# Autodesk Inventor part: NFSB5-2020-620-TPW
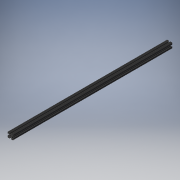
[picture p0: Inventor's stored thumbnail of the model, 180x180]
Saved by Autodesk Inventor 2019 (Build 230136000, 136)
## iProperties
Created: 2022-11
Part Number: NFSB5-2020-620-TPW
Material: Generic
Catalog Web Link: www.cadenas.de
Description: NFS5-2020, NFSB5-2020, HFS5-2020, HFSB5-2020, CAF5-2020, HFSY5-2020, NFSF5-2020, HFSF5-2020, HFSFB5-2020, NFST5-2020, HFST5-2020, HFSTB5-2020, HFSH5-2020, HFSC5
Vendor: MISUMI
Document SubType Name: Modeling
Designer: psAdmin
Manufacturer: MISUMI
Mass: 112.393 g
Surface Area: 1082.73 cm^2
Volume: 112.393 cm^3
Density: 1 g/cm^3
Appearance: PSOLRGB-175-175-175
Category: PARTsolutions
Company: MISUMI
Title: NFSB5-2020-620-TPW
Author: Cadenas PARTsolutions
Comments: HFS5 Series Aluminum Extrusions 20 Square -1 Slot-
PSOL_IDENT_0: {$CADENAS_DATA/23d-libs/misumi/metric/38_al_extrusions_blackets/5/hfs5_2020.prj},686 {VTYP=3D},{NB=N
PSOL_IDENT_1: FSB5-2020-620-TPW},{LINA=NFSB5-2020-620-TPW},{NN=NFS5-2020, NFSB5-2020, HFS5-2020, HFSB5-2020, CAF5-
PSOL_IDENT_2: 2020, HFSY5-2020, NFSF5-2020, HFSF5-2020, HFSFB5-2020, NFST5-2020, HFST5-2020, HFSTB5-2020, HFSH5-20
PSOL_IDENT_3: 20, HFSC5-2020},{DATE=08.06.2021 08:25:16},{GEOMDATE=18.06.2019 07:59:14},{VERSION=},{LINEID=20},{WB
PSOL_IDENT_4: VAR=L,ALT1,ALT2,ALT4,ALT5,CP5,DL5,DR5,ALT6,ALT9,ALT10,ALT11,HP6,NHL6,DL6,NHR6,DR6,ALT7,ALT8,NH9,AH,B
PSOL_IDENT_5: H,CH,DH,EH,NH10,AV,BV,CV,DV,EV,NH11,AP,BP,CP,DP,EP,ALT12,ALT13,Z,NH12,XA,XB,XC,XD,XE,NH13,YA,YB,YC,Y
PSOL_IDENT_6: D,YE,ALT16,HP16,DL16,DR16,ALT17,HQ17,JLP,ALT20},{WBNUMERIC=L,NH9,AH,BH,CH,DH,EH,NH10,AV,BV,CV,DV,EV,
PSOL_IDENT_7: NH11,AP,BP,CP,DP,EP,NH12,XA,XB,XC,XD,XE,NH13,YA,YB,YC,YD,YE,HQ17,JLP}  {NB=NFSB5-2020-620-TPW},{LINA=
PSOL_IDENT_8: NFSB5-2020-620-TPW},{KT=DUMMY},{PN=NFSB5-2020-620-TPW},{TPS=NFSB5-2020},{MAT=6063-T5 Aluminum Alloy}
PSOL_IDENT_9: ,{ST=Black Anodize},{FRMW=20},{FRMH=20},{FRD=4.2},{L=620},{MASS=0.5},{SA=183},{LX=0.742x10^4},{LY=0.
PSOL_IDENT_10: 742x10^4},{ALT1=TPW},{M1=5},{DPL1=15},{DPR1=15},{ALT1PN=-TPW},{ALT2=},{ALT2ALG= '','Not applicable'
PSOL_IDENT_11: },{M2=0},{DP2=0},{ALT2PN=},{ALT4=},{ALT4ALG= '', 'w/o SC (High Precision Cut)', 'SC', 'with SC (High
PSOL_IDENT_12: Precision Cut)' },{ALT4PN=},{ALT5=},{ALT5ALG= '','w/o 45 Degree Cut','1','with 45 Degree Cut' },{CP
PSOL_IDENT_13: 5=},{CP5ALG= '','N/A' },{DL5=},{DL5ALG= '','N/A' },{DR5=},{DR5ALG= '','N/A' },{FRMLALT5=0},{FRMRALT5=
PSOL_IDENT_14: 0},{ALT5PN=},{ALT6=},{ALT6ALG= '','w/o Fastening Location Wrench Access Hole Alterations','1','with
PSOL_IDENT_15: Fastening Location Wrench Access Hole Alterations' },{ALT9=},{ALT9ALG= '','w/o Location Specified Wr
PSOL_IDENT_16: ench Access Hole Alteratons (Horizontal)','1','with Location Specified Wrench Access Hole Alteratons
PSOL_IDENT_17: (Horizontal)' },{ALT10=},{ALT10ALG= '','w/o Location Specified Wrench Access Hole Alteratons (Verti
PSOL_IDENT_18: cal)','1','with Location Specified Wrench Access Hole Alteratons (Vertical)' },{ALT11=},{ALT11ALG= ''
PSOL_IDENT_19: ,'w/o Location Specified Wrench Access Hole Alteratons (Crisscross)','1','with Location Specified Wr
PSOL_IDENT_20: ench Access Hole Alteratons (Crisscross)' },{HP6=},{HP6ALG= '','N/A' },{NHL6=},{NHL6ALG= '','N/A' },
PSOL_IDENT_21: {DL6=},{DL6ALG= '','N/A' },{NHR6=},{NHR6ALG= '','N/A' },{DR6=},{DR6ALG= '','N/A' },{HL6=0.000},{HL6D=
PSOL_IDENT_22: 0},{HR6=0.000},{HR6D=0},{J6=0},{J6D=0},{K6=0},{K6D=0},{DD6=0.00},{DD6ALG=0},{ALT7=},{ALT7ALG= '','N/
PSOL_IDENT_23: A' },{ALT8=},{ALT8ALG= '','N/A' },{ALT678PN=},{NH9=0},{NH9MAX=5},{NH9ALG=[0]},{AH=0.0},{AHMIN=7},{AH
PSOL_IDENT_24: MAX=615},{AHALG=[0]},{BH=0.0},{BHMIN=2},{BHMAX=617},{BHALG=[0]},{CH=0.0},{CHMIN=2},{CHMAX=619},{CHAL
PSOL_IDENT_25: G=[0]},{DH=0.0},{DHMIN=2},{DHMAX=621},{DHALG=[0]},{EH=0.0},{EHMIN=2},{EHMAX=613},{EHALG=[0]},{NH10=0
PSOL_IDENT_26: },{NH10MAX=5},{NH10ALG=[0]},{AV=0.0},{AVMIN=7},{AVMAX=615},{AVALG=[0]},{BV=0.0},{BVMIN=2},{BVMAX=617
PSOL_IDENT_27: },{BVALG=[0]},{CV=0.0},{CVMIN=2},{CVMAX=619},{CVALG=[0]},{DV=0.0},{DVMIN=2},{DVMAX=621},{DVALG=[0]},
PSOL_IDENT_28: {EV=0.0},{EVMIN=2},{EVMAX=613},{EVALG=[0]},{NH11=0},{NH11MAX=5},{NH11ALG=[0]},{AP=0.0},{APMIN=7},{AP
PSOL_IDENT_29: MAX=615},{APALG=[0]},{BP=0.0},{BPMIN=2},{BPMAX=617},{BPALG=[0]},{CP=0.0},{CPMIN=2},{CPMAX=619},{CPAL
PSOL_IDENT_30: G=[0]},{DP=0.0},{DPMIN=2},{DPMAX=621},{DPALG=[0]},{EP=0.0},{EPMIN=2},{EPMAX=613},{EPALG=[0]},{ALT9PN=
PSOL_IDENT_31: },{ALT10PN=},{ALT11PN=},{ALT91011PN=},{ALT12=},{ALT12ALG= '','w/o Counterbore Hole in Specified Posi
PSOL_IDENT_32: tion (Vertical)','1','with Counterbore Hole in Specified Position (Vertical)' },{ALT13=},{ALT13ALG= ''
PSOL_IDENT_33: ,'w/o Counterbore Hole in Specified Position (Horizontal)','1','with Counterbore Hole in Specified P
PSOL_IDENT_34: osition (Horizontal)' },{Z=},{ZALG= '','N/A' },{DD12=0.0},{DD112=0.0},{NH12=0},{NH12MAX=5},{NH12ALG=
PSOL_IDENT_35: [0]},{XA=0.0},{XAMIN=7},{XAMAX=615},{XAALG=[0]},{XB=0.0},{XBMIN=2},{XBMAX=617},{XBALG=[0]},{XC=0.0},
PSOL_IDENT_36: {XCMIN=2},{XCMAX=619},{XCALG=[0]},{XD=0.0},{XDMIN=2},{XDMAX=621},{XDALG=[0]},{XE=0.0},{XEMIN=2},{XEM
PSOL_IDENT_37: AX=613},{XEALG=[0]},{NH13=0},{NH13MAX=5},{NH13ALG=[0]},{YA=0.0},{YAMIN=7},{YAMAX=615},{YAALG=[0]},{Y
PSOL_IDENT_38: B=0.0},{YBMIN=2},{YBMAX=617},{YBALG=[0]},{YC=0.0},{YCMIN=2},{YCMAX=619},{YCALG=[0]},{YD=0.0},{YDMIN=
PSOL_IDENT_39: 2},{YDMAX=621},{YDALG=[0]},{YE=0.0},{YEMIN=2},{YEMAX=613},{YEALG=[0]},{ALT12PN=},{ALT13PN=},{ALT1213
PSOL_IDENT_40: PN=},{ALT16=},{ALT16ALG= '','w/o M Type Hole Alteration','1','with M Type Hole Alteration' },{HP16=}
PSOL_IDENT_41: ,{HP16ALG= '','N/A' },{DL16=},{DL16ALG= '','N/A' },{DR16=},{DR16ALG= '','N/A' },{H116=0},{D16=0.0},{
PSOL_IDENT_42: ALT16PN=},{ALT17=},{ALT17ALG= '','w/o L Type Hole Alteration (Top)','1','with L Type Hole Alteration
PSOL_IDENT_43: (Top)' },{HQ17=0},{HQ17ALG=0},{JLP=0},{JLPMIN=4.9},{JLPMAX=0},{JLPALG=[0]},{L17=0},{D17=0.0},{ALT17
PSOL_IDENT_44: PN=},{ALT20=},{ALT20PN=},{ERRORALT01=OK},{ERRORALT02=OK},{ERRORALT05=OK},{ERRORALT06091=OK},{ERRORAL
PSOL_IDENT_45: T06092=OK},{ERRORALT06093=OK},{ERRORALT06094=OK},{ERRORALT06101=OK},{ERRORALT06102=OK},{ERRORALT0610
PSOL_IDENT_46: 3=OK},{ERRORALT06104=OK},{ERRORALT06111=OK},{ERRORALT06112=OK},{ERRORALT06113=OK},{ERRORALT06114=OK}
PSOL_IDENT_47: ,{ERRORALT06121=OK},{ERRORALT06122=OK},{ERRORALT06123=OK},{ERRORALT06124=OK},{ERRORALT06131=OK},{ERR
PSOL_IDENT_48: ORALT06132=OK},{ERRORALT06133=OK},{ERRORALT06134=OK},{ERRORALT0616=OK},{ERRORALT06171=OK},{ERRORALT0
PSOL_IDENT_49: 6172=OK},{ERRORALT06173=OK},{ERRORALT0911=OK},{ERRORALT0913=OK},{ERRORALT0916=OK},{ERRORALT0917=OK},
PSOL_IDENT_50: {ERRORALT1011=OK},{ERRORALT1012=OK},{ERRORALT1016=OK},{ERRORALT1017=OK},{ERRORALT1112=OK},{ERRORALT1
PSOL_IDENT_51: 113=OK},{ERRORALT1116=OK},{ERRORALT1117=OK},{ERRORALT1216=OK},{ERRORALT1217=OK},{ERRORALT1316=OK},{E
PSOL_IDENT_52: RRORALT1317=OK},{ERRORALT1617=OK},{ERRORPN=},{TFW=0}
NB: NFSB5-2020-620-TPW
NN: NFS5-2020, NFSB5-2020, HFS5-2020, HFSB5-2020, CAF5-2020, HFSY5-2020, NFSF5-2020, HFSF5-2020, HFSFB5-2020, NFST5-2020, HFST5-2020, HFSTB5-2020, HFSH5-2020, HFSC5
NT: HFS5 Series Aluminum Extrusions 20 Square -1 Slot-
NBSYN: $PN.
LINA: NFSB5-2020-620-TPW
CATALOG: Misumi
PN: NFSB5-2020-620-TPW
TPS: NFSB5-2020
MAT: 6063-T5 Aluminum Alloy
ST: Black Anodize
L: 620
MASS: 0.5
SA: 183
LX: 0.742x10^4
LY: 0.742x10^4
ALT1: with TPW (Tapping on Both Ends)
M1: 5
DPL1: 15
DPR1: 15
ALT2: Not applicable
M2: 0
DP2: 0
ALT4: w/o SC (High Precision Cut)
ALT5: w/o 45 Degree Cut
CP5: N/A
DL5: N/A
DR5: N/A
ALT6: w/o Fastening Location Wrench Access Hole Alterations
ALT9: w/o Location Specified Wrench Access Hole Alteratons (Horizontal)
ALT10: w/o Location Specified Wrench Access Hole Alteratons (Vertical)
ALT11: w/o Location Specified Wrench Access Hole Alteratons (Crisscross)
HP6: N/A
NHL6: N/A
DL6: N/A
NHR6: N/A
DR6: N/A
HL6D: 0
HR6D: 0
J6D: 0
K6D: 0
DD6: 0
ALT7: N/A
ALT8: N/A
NH9: 0
AH: 0
BH: 0
CH: 0
DH: 0
EH: 0
NH10: 0
AV: 0
BV: 0
CV: 0
DV: 0
EV: 0
NH11: 0
AP: 0
BP: 0
CP: 0
DP: 0
EP: 0
ALT12: w/o Counterbore Hole in Specified Position (Vertical)
ALT13: w/o Counterbore Hole in Specified Position (Horizontal)
Z: N/A
DD12: 0
DD112: 0
NH12: 0
XA: 0
XB: 0
XC: 0
XD: 0
XE: 0
NH13: 0
YA: 0
YB: 0
YC: 0
YD: 0
YE: 0
ALT16: w/o M Type Hole Alteration
HP16: N/A
DL16: N/A
DR16: N/A
H116: 0
D16: 0
ALT17: w/o L Type Hole Alteration (Top)
HQ17: 0
JLP: 0
D17: 0
ALT20: w/o CW (End Face C Chamfering)
SUPPLIER: MISUMI
ARTICLENO: NFSB5-2020-620-TPW
BOMINFO: NFSB5-2020-620-TPW
CREATOR: CADENAS GmbH
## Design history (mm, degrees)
sketch "Sketch_75"
  geometry: L1 (-10, -3)-(-10, -9); L2 (-9, -10)-(-3, -10); L3 (-3, -10)-(-3, -8); L4 (-3, -8)-(-6, -8); L5 (-6, -8)-(-6, -7.061); L6 (-6, -7.061)-(-2.939, -4); L7 (-2.939, -4)-(-0.654, -4); L8 (-0.404, -3.933)-(0, -3.7); L9 (0, -3.7)-(0.404, -3.933); L10 (0.904, -3.933)-(1.219, -3.751); L11 (1.219, -3.751)-(2.5, -4); L12 (2.5, -4)-(2.939, -4); L13 (2.939, -4)-(6, -7.061); L14 (6, -7.061)-(6, -8); L15 (6, -8)-(3, -8); L16 (3, -8)-(3, -10); L17 (3, -10)-(9, -10); L18 (10, -9)-(10, -3); L19 (10, -3)-(8, -3); L20 (8, -3)-(8, -6); L21 (8, -6)-(7.061, -6); L22 (7.061, -6)-(4, -2.939); L23 (4, -2.939)-(4, -0.654); L24 (3.933, -0.404)-(3.7, 0); L25 (3.7, 0)-(3.933, 0.404); L26 (3.933, 0.904)-(3.751, 1.219); L27 (3.751, 1.219)-(4, 2.5); L28 (4, 2.5)-(4, 2.939); L29 (4, 2.939)-(7.061, 6); L30 (7.061, 6)-(8, 6); L31 (8, 6)-(8, 3); L32 (8, 3)-(10, 3); L33 (10, 3)-(10, 9); L34 (9, 10)-(3, 10); L35 (3, 10)-(3, 8); L36 (3, 8)-(6, 8); L37 (6, 8)-(6, 7.061); L38 (6, 7.061)-(2.939, 4); L39 (2.939, 4)-(0.654, 4); L40 (0.404, 3.933)-(0, 3.7); L41 (0, 3.7)-(-0.404, 3.933); L42 (-0.904, 3.933)-(-1.219, 3.751); L43 (-1.219, 3.751)-(-2.5, 4); L44 (-2.5, 4)-(-2.939, 4); L45 (-2.939, 4)-(-6, 7.061); L46 (-6, 7.061)-(-6, 8); L47 (-6, 8)-(-3, 8); L48 (-3, 8)-(-3, 10); L49 (-3, 10)-(-9, 10); L50 (-10, 9)-(-10, 3); L51 (-10, 3)-(-8, 3); L52 (-8, 3)-(-8, 6); L53 (-8, 6)-(-7.061, 6); L54 (-7.061, 6)-(-4, 2.939); L55 (-4, 2.939)-(-4, 0.654); L56 (-3.933, 0.404)-(-3.7, 0); L57 (-3.7, 0)-(-3.933, -0.404); L58 (-3.933, -0.904)-(-3.751, -1.219); L59 (-3.751, -1.219)-(-4, -2.5); L60 (-4, -2.5)-(-4, -2.939); L61 (-4, -2.939)-(-7.061, -6); L62 (-7.061, -6)-(-8, -6); L63 (-8, -6)-(-8, -3); L64 (-8, -3)-(-10, -3); A1 r 1 centre (-9, -9) between (-10, -9) and (-9, -10); A2 r 0.5 centre (-0.654, -3.5) between (-0.654, -4) and (-0.404, -3.933); A3 r 0.5 centre (0.654, -3.5) between (0.404, -3.933) and (0.904, -3.933); A4 r 1 centre (9, -9) between (9, -10) and (10, -9); A5 r 0.5 centre (3.5, -0.654) between (4, -0.654) and (3.933, -0.404); A6 r 0.5 centre (3.5, 0.654) between (3.933, 0.404) and (3.933, 0.904); A7 r 1 centre (9, 9) between (10, 9) and (9, 10); A8 r 0.5 centre (0.654, 3.5) between (0.654, 4) and (0.404, 3.933); A9 r 0.5 centre (-0.654, 3.5) between (-0.404, 3.933) and (-0.904, 3.933); A10 r 1 centre (-9, 9) between (-9, 10) and (-10, 9); A11 r 0.5 centre (-3.5, 0.654) between (-4, 0.654) and (-3.933, 0.404); A12 r 0.5 centre (-3.5, -0.654) between (-3.933, -0.404) and (-3.933, -0.904)
  constraints: 128 end point, 24 point on circle, 12 centre point
extrude "Extrusion1" join sketch "Sketch_75" distance "d0" = 620; taper "d1" = 0 deg
sketch "Sketch2"
  geometry: 1 further point
hole "Hole1" sketch "Sketch2" at (0, 0) diameter "d2" = 4.134; stored, may be unused: countersink angle "d6" = 90 deg, drill point angle "d8" = 0 deg; dims "d3" = 15, "d4" = 5, "d5" = 2, "d7" = 15
sketch "Sketch3"
  geometry: 1 further point
hole "Hole2" sketch "Sketch3" at (0, 0) diameter "d9" = 4.134; stored, may be unused: countersink angle "d13" = 90 deg, drill point angle "d15" = 0 deg; dims "d10" = 15, "d11" = 5, "d12" = 2, "d14" = 15
sketch "Sketch4"
  geometry: 1 further point
hole "Hole3" sketch "Sketch4" at (0, 0) diameter "d16" = 4.2; stored, may be unused: countersink angle "d20" = 90 deg, drill point angle "d22" = 0 deg; dims "d17" = 6, "d18" = 4, "d19" = 2, "d21" = 590
node "C1_XY"
node "C1_YZ"
node "C1_ZX"
node "C1_X"
node "C1_Y"
node "C1_Z"
node "C1_Center"
body "Solid1"
other parameters: "d23" = 0
